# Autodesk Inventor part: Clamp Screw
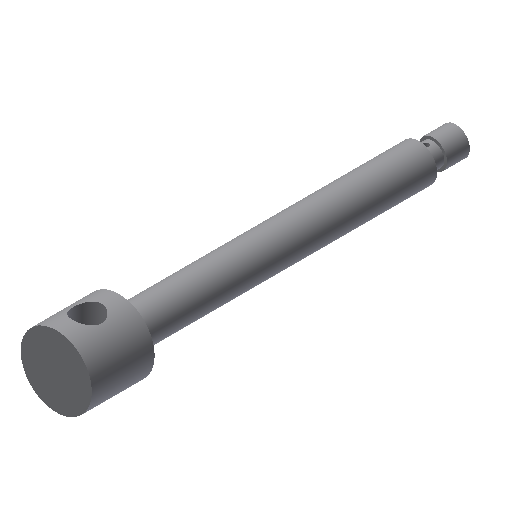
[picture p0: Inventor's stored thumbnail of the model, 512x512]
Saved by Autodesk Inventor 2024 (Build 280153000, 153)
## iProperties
Shininess: 77.0
Length Units: 11269
Angle Units: 11279
Time Units: 11290
Mass Units: 11283
Length Display Precision: 3
Angle Display Precision: 2
Created: 2002-02
Part Number: Clamp Screw
Document SubType Name: Modeling
Designer: ***
Density: 1 g/cm^3
Material: Generic
Mass: 23.4191 g
Surface Area: 81.8482 cm^2
Volume: 23.4191 cm^3
Appearance: Default
Density: 0.0
Volumn: 0.0
Area: 0.0
PropertySet Name: Model Information
Control State: 0
Master: False
Checked Out: False
Author: ***
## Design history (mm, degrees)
sketch "Sketch1"
  geometry: L1 (0, 140)-(5, 140); L2 (5, 140)-(5, 132); L3 (5, 132)-(4, 132); L4 (4, 132)-(4, 127); L5 (4, 127)-(6.5, 127); L6 (6.5, 127)-(6.5, 25); L7 (6.5, 25)-(4, 25); L8 (4, 25)-(4, 22); L9 (4, 22)-(12.5, 22); L10 (12.5, 22)-(12.5, 0); L11 (12.5, 0)-(0, 0); L12 (0, 0)-(0, 140)
  constraints: 24 end point, 10 parallel, 1 horizontal, 1 perpendicular
  dimensions: "d0" = 10 diameter of L2 L12; "d1" = 8 diameter of L4 L12; "d2" = 13 diameter of L6 L12; "d3" = 8 diameter of L7.end L12; "d4" = 25 diameter of L10 L12; "d5" = 3 distance from line of L7.end L9; "d6" = 8 distance of L1.end L2.end; "d7" = 13 vertical distance of L1.end L5.end; "d8" = 22 distance of L9.end L10.end; "d10" = 102 distance of L5.end L6.end
revolve "Revolution1" sketch "Sketch1" stored, may be unused: angle "d11" = 90 deg
sketch "Sketch3"
  geometry: L1 (-12.5, 0)-(12.5, 0) reference; C1 r 5 at (-0.113, 11)
  constraints: 1 centre point
  dimensions: "d13" = 10 diameter of C1; "d14" = 11 distance from line of L1 C1.centre
extrude "Extrusion1" cut sketch "Sketch3" extent not by distance; stored distance "d15" = 10; taper "d16" = 0 deg
sketch "Sketch4"
  geometry: L1 (0, 138.841)-(0, 0); L2 (-12.5, 0)-(12.5, 0) reference; L3 (-5, 140)-(5, 140) reference; C1 r 1 at (0, 129.5)
  constraints: 2 end point, 1 centre point, 1 point on line, 1 vertical
  dimensions: "d17" = 2 diameter of C1; "d18" = 10.5 distance from line of L3 C1.centre
extrude "Extrusion2" cut sketch "Sketch4" stored distance "d19" = 10; taper "d20" = 0 deg
body "Solid1"
